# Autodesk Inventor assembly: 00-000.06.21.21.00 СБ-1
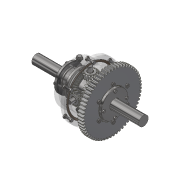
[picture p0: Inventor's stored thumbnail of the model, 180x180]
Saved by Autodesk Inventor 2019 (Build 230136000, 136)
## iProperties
Created: 2019-01
Part Number: 00-000.06.21.21.00 СБ-1
Document SubType Name: Assembly
Designer: m.vorobev
Author: m.vorobev
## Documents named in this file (31)
- C:\Users\m.vorobev.TRINITY\Documents\Inventor\00-000.06.21.21.00\00-000.06.21.21.00 СБ-1.iam
- C:\Users\m.vorobev.TRINITY\Documents\Inventor\00-000.06.21.21.00\00-000.06.21.21.10.ipt
- C:\Users\m.vorobev.TRINITY\Documents\Inventor\00-000.06.21.21.00\00-000.06.21.21.01.ipt
- C:\Users\m.vorobev.TRINITY\Documents\Inventor\00-000.06.21.21.00\00-000.06.21.21.02.ipt
- C:\Users\m.vorobev.TRINITY\Documents\Inventor\00-000.06.21.21.00\Content Center Files\en-US\Bolt GOST 7798-78\Bolt  M10-6g×35(S16) GOST 7798-70.ipt
- C:\Users\m.vorobev.TRINITY\Documents\Inventor\00-000.06.21.21.00\Content Center Files\en-US\GOST 6402-70\Washer  10 L GOST 6402-70.ipt
- C:\Users\m.vorobev.TRINITY\Documents\Inventor\00-000.06.21.21.00\Content Center Files\en-US\GOST 5916-70\Nut M10-6H GOST 5916-70.ipt
- C:\Users\m.vorobev.TRINITY\Documents\Inventor\00-000.06.21.21.00\00-000.06.21.21.15.ipt
- C:\Users\m.vorobev.TRINITY\Documents\Inventor\00-000.06.21.21.00\00-000.06.21.21.05.ipt
- C:\Users\m.vorobev.TRINITY\Documents\Inventor\00-000.06.21.21.00\Key 2-36x20x100 GOST 23360-78.ipt
- C:\Users\m.vorobev.TRINITY\Documents\Inventor\00-000.06.21.21.00\Content Center Files\en-US\Stud GOST 22034-76\Stud M10-6g×45 GOST 22034-76.ipt
- C:\Users\m.vorobev.TRINITY\Documents\Inventor\00-000.06.21.21.00\00-000.06.21.21.07.ipt
- C:\Users\m.vorobev.TRINITY\Documents\Inventor\00-000.06.21.21.00\00-000.06.21.21.11,12,13\00-000.06.21.21.12.ipt
- C:\Users\m.vorobev.TRINITY\Documents\Inventor\00-000.06.21.21.00\00-000.06.21.21.11,12,13.ipt
- C:\Users\m.vorobev.TRINITY\Documents\Inventor\00-000.06.21.21.00\00-000.06.21.21.03.ipt
- C:\Users\m.vorobev.TRINITY\Documents\Inventor\00-000.06.21.21.00\00-000.06.21.21.04.ipt
- C:\Users\m.vorobev.TRINITY\Documents\Inventor\00-000.06.21.21.00\Key 2-12x8x28 GOST 23360-78.ipt
- C:\Users\m.vorobev.TRINITY\Documents\Inventor\00-000.06.21.21.00\Content Center Files\en-US\Nut GOST 12460-67\Nut 7003-0141 GOST 12460-67.ipt
- C:\Users\m.vorobev.TRINITY\Documents\Inventor\00-000.06.21.21.00\00-000.06.21.21.11,12,13\00-000.06.21.21.11.ipt
- C:\Users\m.vorobev.TRINITY\Documents\Inventor\00-000.06.21.21.00\Content Center Files\en-US\GOST 8338-75\Bearing 309 GOST 8338-75.ipt
- C:\Users\m.vorobev.TRINITY\Documents\Inventor\00-000.06.21.21.00\00-000.06.21.21.11,12,13\00-000.06.21.21.13.ipt
- C:\Users\m.vorobev.TRINITY\Documents\Inventor\00-000.06.21.21.00\00-000.06.21.21.08,09\00-000.06.21.21.08.ipt
- C:\Users\m.vorobev.TRINITY\Documents\Inventor\00-000.06.21.21.00\00-000.06.21.21.08,09.ipt
- C:\Users\m.vorobev.TRINITY\Documents\Inventor\00-000.06.21.21.00\00-000.06.21.21.08,09\00-000.06.21.21.09.ipt
- C:\Users\m.vorobev.TRINITY\Documents\Inventor\00-000.06.21.21.00\00-000.06.21.21.29.ipt
- C:\Users\m.vorobev.TRINITY\Documents\Inventor\00-000.06.21.21.00\Content Center Files\en-US\GOST 6402-70\Washer  8 L GOST 6402-70.ipt
- C:\Users\m.vorobev.TRINITY\Documents\Inventor\00-000.06.21.21.00\Content Center Files\en-US\Bolt GOST 7798-78\Bolt  M8-6g×35(S13) GOST 7798-70.ipt
- C:\Users\m.vorobev.TRINITY\Documents\Inventor\00-000.06.21.21.00\00-000.06.21.21.06.ipt
- C:\Users\m.vorobev.TRINITY\Documents\Inventor\00-000.06.21.21.00\00-000.06.21.21.17.ipt
- C:\Users\m.vorobev.TRINITY\Documents\Inventor\00-000.06.21.21.00\00-000.06.21.21.16.ipt
- C:\Users\m.vorobev.TRINITY\Documents\Inventor\00-000.06.21.21.00\00-000.06.21.21.14.ipt
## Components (106 placed, 28 different names)
1. 00-000.06.21.21.05:1 — Angle:1, Insert:21, Flush:1, Angle:4, Mate:25
2. 00-000.06.21.21.10:1 — Mate:4, Mate:5, Mate:6, Mate:7, Mate:8, Mate:16, Mate:23
3. 00-000.06.21.21.01:1 — Mate:19, Insert:70, Mate:21, Insert:90, Mate:22, Insert:93, Insert:95, Insert:97, Mate:24, Mate:26
4. 00-000.06.21.21.02:1 — Insert:19, Mate:1, Mate:2, Mate:3, Insert:20, Insert:21, Mate:18, Insert:53, Insert:71, Mate:20, Mate:23, Insert:95
5. 00-000.06.21.21.15:1 — Insert:19
6. Key 2-36x20x100 GOST 23360-78:1 — Mate:1, Mate:2, Mate:3, Angle:1
7. 00-000.06.21.21.07:1 — Mate:14, Insert:44, Mate:15, Mate:17, Insert:45, Insert:46, Insert:47, Insert:48, Mate:24
8. 00-000.06.21.21.12:1 — Insert:38, Insert:44
9. 00-000.06.21.21.12:2 — Insert:39, Insert:47
10. 00-000.06.21.21.12:3 — Insert:41, Insert:46
11. 00-000.06.21.21.12:4 — Insert:40, Insert:45
12. 00-000.06.21.21.03:1 — Insert:38, Rotation:3
13. 00-000.06.21.21.03:2 — Insert:39, Rotation:2
14. 00-000.06.21.21.03:3 — Insert:40, Rotation:4
15. 00-000.06.21.21.03:4 — Insert:41, Rotation:2, Rotation:3, Rotation:4, Rotation:5
16. 00-000.06.21.21.04:1 — Mate:7, Angle:2, Mate:8, Insert:42, Mate:15, Insert:49, Rotation:1, Rotation:5, Rotating
17. Key 2-12x8x28 GOST 23360-78:1 — Mate:4, Mate:5, Mate:6, Angle:2
18. 00-000.06.21.21.10:2 — Mate:16, Mate:22
19. 00-000.06.21.21.04:2 — Mate:17, Insert:50, Rotation:1
20. Key 2-12x8x28 GOST 23360-78:2
21. 00-000.06.21.21.11:5 — Insert:48
22. 00-000.06.21.21.13:6 — Insert:49
23. 00-000.06.21.21.13:7 — Insert:50
24. 00-000.06.21.21.08:1 — Insert:51, Mate:18, Insert:53, Insert:80
25. 00-000.06.21.21.09:2 — Insert:52, Insert:63, Insert:67, Insert:68, Insert:69, Mate:19, Insert:70, Insert:89, Insert:91
26. 00-000.06.21.21.29:1 — Insert:51
27. 00-000.06.21.21.29:2 — Insert:52
28. 00-000.06.21.21.06:1 — Insert:71, Mate:20, Insert:76, Insert:77, Insert:78, Insert:79
29. 00-000.06.21.21.06:2 — Mate:21, Insert:90
30. 00-000.06.21.21.17:1 — Insert:93, Insert:94
31. 00-000.06.21.21.16:1 — Insert:91
32. 00-000.06.21.21.14:1 — Insert:94
33. 00-000.06.21.21.17:2 — Insert:97
34. 00-000.06.21.21.14:2
35. Bolt GOST 7798-70 M10-6g×35(S16):1
36. Bolt GOST 7798-70 M10-6g×35(S16):2
37. Bolt GOST 7798-70 M10-6g×35(S16):3
38. Bolt GOST 7798-70 M10-6g×35(S16):4
39. Bolt GOST 7798-70 M10-6g×35(S16):5
40. Bolt GOST 7798-70 M10-6g×35(S16):6
41. Washer GOST 6402-70 10 L:1
42. Washer GOST 6402-70 10 L:2
43. Washer GOST 6402-70 10 L:3
44. Washer GOST 6402-70 10 L:4
45. Washer GOST 6402-70 10 L:5
46. Washer GOST 6402-70 10 L:6
47. Nut GOST 5916-70 M10:1
48. Nut GOST 5916-70 M10:2
49. Nut GOST 5916-70 M10:3
50. Nut GOST 5916-70 M10:4
51. Nut GOST 5916-70 M10:5
52. Nut GOST 5916-70 M10:6
53. Washer GOST 6402-70 10 L:7 — Insert:28
54. Washer GOST 6402-70 10 L:8 — Insert:33
55. Washer GOST 6402-70 10 L:9 — Insert:32
56. Washer GOST 6402-70 10 L:10 — Insert:31
57. Washer GOST 6402-70 10 L:11 — Insert:30
58. Washer GOST 6402-70 10 L:12 — Insert:29
59. Nut GOST 5916-70 M10:7 — Insert:28
60. Nut GOST 5916-70 M10:8 — Insert:33
61. Nut GOST 5916-70 M10:9 — Insert:29
62. Nut GOST 5916-70 M10:10 — Insert:30
63. Nut GOST 5916-70 M10:11 — Insert:31
64. Nut GOST 5916-70 M10:12 — Insert:32
65. Nut GOST 12460-67 7003-0141:1 — Insert:42, Mate:14
66. Nut GOST 12460-67 7003-0141:3
67. Bearing GOST 8338-75 309:1 — Insert:89
68. Washer GOST 6402-70 8 L:1
69. Washer GOST 6402-70 8 L:2 — Insert:59
70. Washer GOST 6402-70 8 L:3 — Insert:61
71. Washer GOST 6402-70 8 L:4 — Insert:60
72. Bolt GOST 7798-70 M8-6g×35(S13):1
73. Bolt GOST 7798-70 M8-6g×35(S13):2 — Insert:59
74. Bolt GOST 7798-70 M8-6g×35(S13):3 — Insert:61
75. Bolt GOST 7798-70 M8-6g×35(S13):4 — Insert:60
76. Washer GOST 6402-70 8 L:5 — Insert:63
77. Bolt GOST 7798-70 M8-6g×35(S13):5
78. Washer GOST 6402-70 8 L:6 — Insert:68
79. Bolt GOST 7798-70 M8-6g×35(S13):6
80. Washer GOST 6402-70 8 L:7 — Insert:69
81. Bolt GOST 7798-70 M8-6g×35(S13):7
82. Washer GOST 6402-70 8 L:8 — Insert:67
83. Bolt GOST 7798-70 M8-6g×35(S13):8
84. Washer GOST 6402-70 8 L:9 — Insert:78
85. Bolt GOST 7798-70 M8-6g×35(S13):9
86. Washer GOST 6402-70 8 L:10 — Insert:76
87. Bolt GOST 7798-70 M8-6g×35(S13):10
88. Washer GOST 6402-70 8 L:11 — Insert:79
89. Bolt GOST 7798-70 M8-6g×35(S13):11
90. Washer GOST 6402-70 8 L:12 — Insert:77
91. Bolt GOST 7798-70 M8-6g×35(S13):12
92. Bearing GOST 8338-75 309:2 — Insert:80
93. Washer GOST 6402-70 8 L:13
94. Bolt GOST 7798-70 M8-6g×35(S13):13
95. Washer GOST 6402-70 8 L:14
96. Bolt GOST 7798-70 M8-6g×35(S13):14
97. Washer GOST 6402-70 8 L:15
98. Bolt GOST 7798-70 M8-6g×35(S13):15
99. Washer GOST 6402-70 8 L:16
100. Bolt GOST 7798-70 M8-6g×35(S13):16
101. Stud GOST 22034-76 M10-6g×45:1 — Insert:20
102. Stud GOST 22034-76 M10-6g×45:2
103. Stud GOST 22034-76 M10-6g×45:3
104. Stud GOST 22034-76 M10-6g×45:4
105. Stud GOST 22034-76 M10-6g×45:5
106. Stud GOST 22034-76 M10-6g×45:6
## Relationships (76: Insert 45, Mate 21, RelateRotation 5, Angle 4, Flush 1)
- Insert:19: 00-000.06.21.21.02:1 ↔ 00-000.06.21.21.15:1
- Mate:1: 00-000.06.21.21.02:1 ↔ Key 2-36x20x100 GOST 23360-78:1
- Mate:2: 00-000.06.21.21.02:1 ↔ Key 2-36x20x100 GOST 23360-78:1
- Mate:3: 00-000.06.21.21.02:1 ↔ Key 2-36x20x100 GOST 23360-78:1
- Insert:20: 00-000.06.21.21.02:1 ↔ Stud GOST 22034-76 M10-6g×45:1
- Angle:1: 00-000.06.21.21.05:1 ↔ Key 2-36x20x100 GOST 23360-78:1
- Insert:21: 00-000.06.21.21.05:1 ↔ 00-000.06.21.21.02:1
- Insert:28: Washer GOST 6402-70 10 L:7 ↔ Nut GOST 5916-70 M10:7
- Insert:29: Washer GOST 6402-70 10 L:12 ↔ Nut GOST 5916-70 M10:9
- Insert:30: Washer GOST 6402-70 10 L:11 ↔ Nut GOST 5916-70 M10:10
- Insert:31: Washer GOST 6402-70 10 L:10 ↔ Nut GOST 5916-70 M10:11
- Insert:32: Washer GOST 6402-70 10 L:9 ↔ Nut GOST 5916-70 M10:12
- Insert:33: Washer GOST 6402-70 10 L:8 ↔ Nut GOST 5916-70 M10:8
- Insert:38: 00-000.06.21.21.12:1 ↔ 00-000.06.21.21.03:1
- Insert:39: 00-000.06.21.21.12:2 ↔ 00-000.06.21.21.03:2
- Insert:40: 00-000.06.21.21.12:4 ↔ 00-000.06.21.21.03:3
- Insert:41: 00-000.06.21.21.12:3 ↔ 00-000.06.21.21.03:4
- Mate:4: 00-000.06.21.21.10:1 ↔ Key 2-12x8x28 GOST 23360-78:1
- Mate:5: 00-000.06.21.21.10:1 ↔ Key 2-12x8x28 GOST 23360-78:1
- Mate:6: 00-000.06.21.21.10:1 ↔ Key 2-12x8x28 GOST 23360-78:1
- Mate:7: 00-000.06.21.21.10:1 ↔ 00-000.06.21.21.04:1
- Angle:2: 00-000.06.21.21.04:1 ↔ Key 2-12x8x28 GOST 23360-78:1
- Mate:8: 00-000.06.21.21.10:1 ↔ 00-000.06.21.21.04:1
- Insert:42: 00-000.06.21.21.04:1 ↔ Nut GOST 12460-67 7003-0141:1
- Mate:14: 00-000.06.21.21.07:1 ↔ Nut GOST 12460-67 7003-0141:1
- Insert:44: 00-000.06.21.21.07:1 ↔ 00-000.06.21.21.12:1
- Mate:15: 00-000.06.21.21.07:1 ↔ 00-000.06.21.21.04:1
- Mate:16: 00-000.06.21.21.10:1 ↔ 00-000.06.21.21.10:2
- Mate:17: 00-000.06.21.21.07:1 ↔ 00-000.06.21.21.04:2
- Insert:45: 00-000.06.21.21.07:1 ↔ 00-000.06.21.21.12:4
- Insert:46: 00-000.06.21.21.07:1 ↔ 00-000.06.21.21.12:3
- Insert:47: 00-000.06.21.21.07:1 ↔ 00-000.06.21.21.12:2
- Insert:48: 00-000.06.21.21.07:1 ↔ 00-000.06.21.21.11:5
- Insert:49: 00-000.06.21.21.04:1 ↔ 00-000.06.21.21.13:6
- Insert:50: 00-000.06.21.21.04:2 ↔ 00-000.06.21.21.13:7
- Insert:51: 00-000.06.21.21.08:1 ↔ 00-000.06.21.21.29:1
- Insert:52: 00-000.06.21.21.09:2 ↔ 00-000.06.21.21.29:2
- Mate:18: 00-000.06.21.21.02:1 ↔ 00-000.06.21.21.08:1
- Insert:53: 00-000.06.21.21.02:1 ↔ 00-000.06.21.21.08:1
- Insert:59: Washer GOST 6402-70 8 L:2 ↔ Bolt GOST 7798-70 M8-6g×35(S13):2
- Insert:60: Washer GOST 6402-70 8 L:4 ↔ Bolt GOST 7798-70 M8-6g×35(S13):4
- Insert:61: Washer GOST 6402-70 8 L:3 ↔ Bolt GOST 7798-70 M8-6g×35(S13):3
- Insert:63: 00-000.06.21.21.09:2 ↔ Washer GOST 6402-70 8 L:5
- Insert:67: 00-000.06.21.21.09:2 ↔ Washer GOST 6402-70 8 L:8
- Insert:68: 00-000.06.21.21.09:2 ↔ Washer GOST 6402-70 8 L:6
- Insert:69: 00-000.06.21.21.09:2 ↔ Washer GOST 6402-70 8 L:7
- Mate:19: 00-000.06.21.21.01:1 ↔ 00-000.06.21.21.09:2
- Insert:70: 00-000.06.21.21.01:1 ↔ 00-000.06.21.21.09:2
- Insert:71: 00-000.06.21.21.02:1 ↔ 00-000.06.21.21.06:1
- Mate:20: 00-000.06.21.21.02:1 ↔ 00-000.06.21.21.06:1
- Insert:76: 00-000.06.21.21.06:1 ↔ Washer GOST 6402-70 8 L:10
- Insert:77: 00-000.06.21.21.06:1 ↔ Washer GOST 6402-70 8 L:12
- Insert:78: 00-000.06.21.21.06:1 ↔ Washer GOST 6402-70 8 L:9
- Insert:79: 00-000.06.21.21.06:1 ↔ Washer GOST 6402-70 8 L:11
- Insert:80: 00-000.06.21.21.08:1 ↔ Bearing GOST 8338-75 309:2
- Mate:21: 00-000.06.21.21.01:1 ↔ 00-000.06.21.21.06:2
- Insert:89: 00-000.06.21.21.09:2 ↔ Bearing GOST 8338-75 309:1
- Insert:90: 00-000.06.21.21.01:1 ↔ 00-000.06.21.21.06:2
- Mate:22: 00-000.06.21.21.01:1 ↔ 00-000.06.21.21.10:2
- Mate:23: 00-000.06.21.21.10:1 ↔ 00-000.06.21.21.02:1
- Insert:91: 00-000.06.21.21.09:2 ↔ 00-000.06.21.21.16:1
- Insert:93: 00-000.06.21.21.01:1 ↔ 00-000.06.21.21.17:1
- Insert:94: 00-000.06.21.21.17:1 ↔ 00-000.06.21.21.14:1
- Insert:95: 00-000.06.21.21.01:1 ↔ 00-000.06.21.21.02:1
- Flush:1: 00-000.06.21.21.05:1
- Angle:4: 00-000.06.21.21.05:1
- Insert:97: 00-000.06.21.21.01:1 ↔ 00-000.06.21.21.17:2
- Mate:24: 00-000.06.21.21.01:1 ↔ 00-000.06.21.21.07:1
- Mate:25: 00-000.06.21.21.05:1
- Rotation:1 [RelateRotation]: 00-000.06.21.21.04:1 ↔ 00-000.06.21.21.04:2
- Rotation:2 [RelateRotation]: 00-000.06.21.21.03:2 ↔ 00-000.06.21.21.03:4
- Rotation:3 [RelateRotation]: 00-000.06.21.21.03:1 ↔ 00-000.06.21.21.03:4
- Rotation:4 [RelateRotation]: 00-000.06.21.21.03:3 ↔ 00-000.06.21.21.03:4
- Rotation:5 [RelateRotation]: 00-000.06.21.21.03:4 ↔ 00-000.06.21.21.04:1
- Rotating [Angle]: 00-000.06.21.21.04:1
- Mate:26: 00-000.06.21.21.01:1
## Named parameters: d52_d49 = 0, d54_d51 = 0, d55_d45 = 0, d56_d46 = 0, d57_d47 = 0, d58_d48 = 0, d88_d84 = 0, d90_d88_d84 = 0, d91_d88_d84 = 0, d92_d88_d84 = 0, d100_d84 = 0, d101_d100_d84 = 0, d102_d100_d84 = 0, d103_d100_d84 = 0, d109_d100_d84 = 0, d110_d101_d100_d84 = 0, d111_d102_d100_d84 = 0, d112_d103_d100_d84 = 0, d113_d104 = 0, d114_d105 = 0, d115_d106 = 0, d116_d107 = 0, d139_d125 = 0
